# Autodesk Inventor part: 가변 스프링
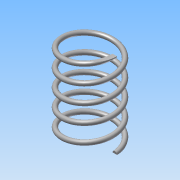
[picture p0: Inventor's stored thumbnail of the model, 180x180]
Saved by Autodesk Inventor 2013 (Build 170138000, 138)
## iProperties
Created: 2015-10
Part Number: 가변 스프링
Material: 강철, 연강
Document SubType Name: Modeling
Designer: Administrator
Density: 7.86 g/cm^3
Mass: 1.05581 g
Surface Area: 5.42544 cm^2
Volume: 0.134327 cm^3
Author: Administrator
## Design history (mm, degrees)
sketch "스케치1"
  geometry: L1 (0, 0)-(5.5, 0); L2 (5.5, 0)-(5.5, 18.948); L3 (5.5, 18.948)-(0, 18.948); L4 (0, 18.948)-(0, 0); C1 r 0.5 at (5.5, 0)
  constraints: 8 end point, 2 parallel, 1 centre point, 1 coincident, 1 horizontal, 1 perpendicular
  dimensions: "d0" = 11 diameter of L2 L4; "d2" = 18.94782 distance of L1.end L2.end (derived); "d3" = 1 diameter of C1
feature "코일1" sketch "스케치1" pitch "d4" = 10; turns "d6" = 5; dims "d5" = 18.94782 (= d2), "d7" = 0, angle "d8" = 90 deg, angle "d9" = 90 deg, "d10" = 0, "d11" = 0
node "작업 평면1"
feature "분할1"
node "작업 평면2"
feature "분할2"
node "솔리드1"
other parameters: "d12" = 90 deg, "d13" = 90 deg
